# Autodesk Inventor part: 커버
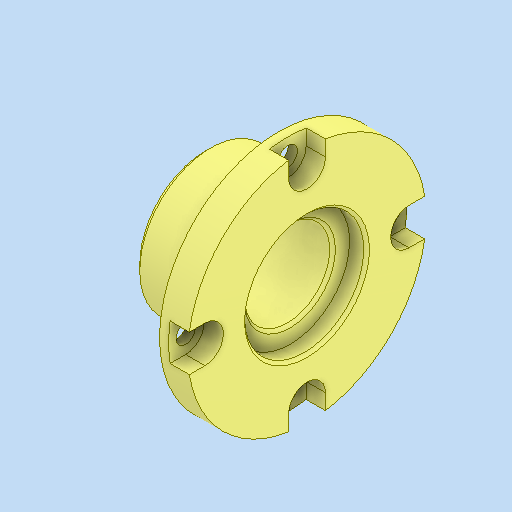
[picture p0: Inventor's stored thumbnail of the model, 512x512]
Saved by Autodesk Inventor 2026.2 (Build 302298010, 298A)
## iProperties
Created: 2026-08
Part Number: 커버
Material: 알루미늄 6061
Document SubType Name: Modeling
Designer: PC-2-06
Density: 2.71 g/cm^3
Appearance: 기본값
Author: jhkim
Sending System: Autodesk Inventor 2027
Preprocessor: ST-DEVELOPER v20.1
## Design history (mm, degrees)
feature "솔리드1"
node "솔리드2"
